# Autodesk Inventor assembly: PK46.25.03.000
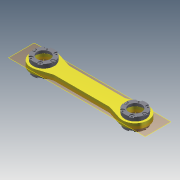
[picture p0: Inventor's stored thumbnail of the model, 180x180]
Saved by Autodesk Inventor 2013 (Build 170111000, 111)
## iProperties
Created: 2005-04
Part Number: PK46.25.03.000
Document SubType Name: Assembly
Designer: salex
Manufacturer: Standard
Standards Organization: Custom
Author: salex
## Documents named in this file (12)
- D:\FrontLoaderVault\Data\Assy, Chassis, Front\PK46.25.03.000.iam
- D:\FrontLoaderVault\Data\Assy, Chassis, Front\PK46.25.03.010.iam
- D:\FrontLoaderVault\Data\Assy, Chassis, Front\PK46.25.01.014.ipt
- D:\FrontLoaderVault\Data\Assy, Chassis, Front\PK46.25.01.015.ipt
- D:\FrontLoaderVault\Data\Assy, Chassis, Front\M10-6H.5.019(S16).ipt
- D:\FrontLoaderVault\Data\Assy, Chassis, Front\10.65G.019.ipt
- D:\FrontLoaderVault\Data\Assy, Chassis, Front\PK46.25.00.005.ipt
- D:\FrontLoaderVault\Data\Assy, Chassis, Front\PK46.25.00.010.iam
- D:\FrontLoaderVault\Data\Assy, Chassis, Front\PK46.25.00.007.ipt
- D:\FrontLoaderVault\Data\Assy, Chassis, Front\PK46.25.00.008.ipt
- M10-6H.5.019(S16).ipt
- 10.65G.019.ipt
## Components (22 placed, 9 different names)
1. PK46.25.03.010:1 [sub-assembly] — Insert:1, Insert:2, Insert:3, Insert:4, Mate:1, Mate:2, Mate:3, Mate:4, Angle:1, Angle:2, Angle:3, Angle:4
2. PK46.25.01.014:1 — Insert:1, Mate:1, Insert:14, Insert:13
3. PK46.25.01.014:2 — Insert:2, Mate:2, Insert:5, Insert:6
4. PK46.25.01.014:3 — Insert:4, Mate:4, Insert:15, Insert:16
5. PK46.25.01.014:4 — Insert:3, Mate:3, Insert:10, Insert:9
6. PK46.25.01.015:1 — Insert:13
7. PK46.25.01.015:2 — Insert:14
8. PK46.25.01.015:3 — Insert:6
9. PK46.25.01.015:4 — Insert:5
10. M10-6H.5.019(S16):1 — Insert:12, Angle:2
11. M10-6H.5.019(S16):2 — Insert:11, Angle:1
12. M10-6H.5.019(S16):3 — Insert:7, Angle:4
13. M10-6H.5.019(S16):4 — Insert:8, Angle:3
14. 10.65G.019:1 — Insert:12, Insert:15
15. 10.65G.019:2 — Insert:11, Insert:16
16. 10.65G.019:3 — Insert:7, Insert:9
17. 10.65G.019:4 — Insert:8, Insert:10
18. PK46.25.00.007:1
19. PK46.25.00.008:1
20. PK46.25.00.005:1
21. PK46.25.00.010:1 [sub-assembly]
22. PK46.25.00.005:2
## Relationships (24: Insert 16, Mate 4, Angle 4)
- Insert:1: PK46.25.03.010:1 ↔ PK46.25.01.014:1
- Insert:2: PK46.25.03.010:1 ↔ PK46.25.01.014:2
- Insert:3: PK46.25.03.010:1 ↔ PK46.25.01.014:4
- Insert:4: PK46.25.03.010:1 ↔ PK46.25.01.014:3
- Mate:1: PK46.25.03.010:1 ↔ PK46.25.01.014:1
- Mate:2: PK46.25.03.010:1 ↔ PK46.25.01.014:2
- Mate:3: PK46.25.03.010:1 ↔ PK46.25.01.014:4
- Mate:4: PK46.25.03.010:1 ↔ PK46.25.01.014:3
- Insert:7: M10-6H.5.019(S16):3 ↔ 10.65G.019:3
- Insert:8: M10-6H.5.019(S16):4 ↔ 10.65G.019:4
- Insert:11: M10-6H.5.019(S16):2 ↔ 10.65G.019:2
- Insert:12: M10-6H.5.019(S16):1 ↔ 10.65G.019:1
- Angle:1: PK46.25.03.010:1 ↔ M10-6H.5.019(S16):2
- Angle:2: PK46.25.03.010:1 ↔ M10-6H.5.019(S16):1
- Angle:3: PK46.25.03.010:1 ↔ M10-6H.5.019(S16):4
- Angle:4: PK46.25.03.010:1 ↔ M10-6H.5.019(S16):3
- Insert:5: PK46.25.01.014:2 ↔ PK46.25.01.015:4
- Insert:6: PK46.25.01.014:2 ↔ PK46.25.01.015:3
- Insert:14: PK46.25.01.014:1 ↔ PK46.25.01.015:2
- Insert:13: PK46.25.01.014:1 ↔ PK46.25.01.015:1
- Insert:15: PK46.25.01.014:3 ↔ 10.65G.019:1
- Insert:16: PK46.25.01.014:3 ↔ 10.65G.019:2
- Insert:10: PK46.25.01.014:4 ↔ 10.65G.019:4
- Insert:9: PK46.25.01.014:4 ↔ 10.65G.019:3
